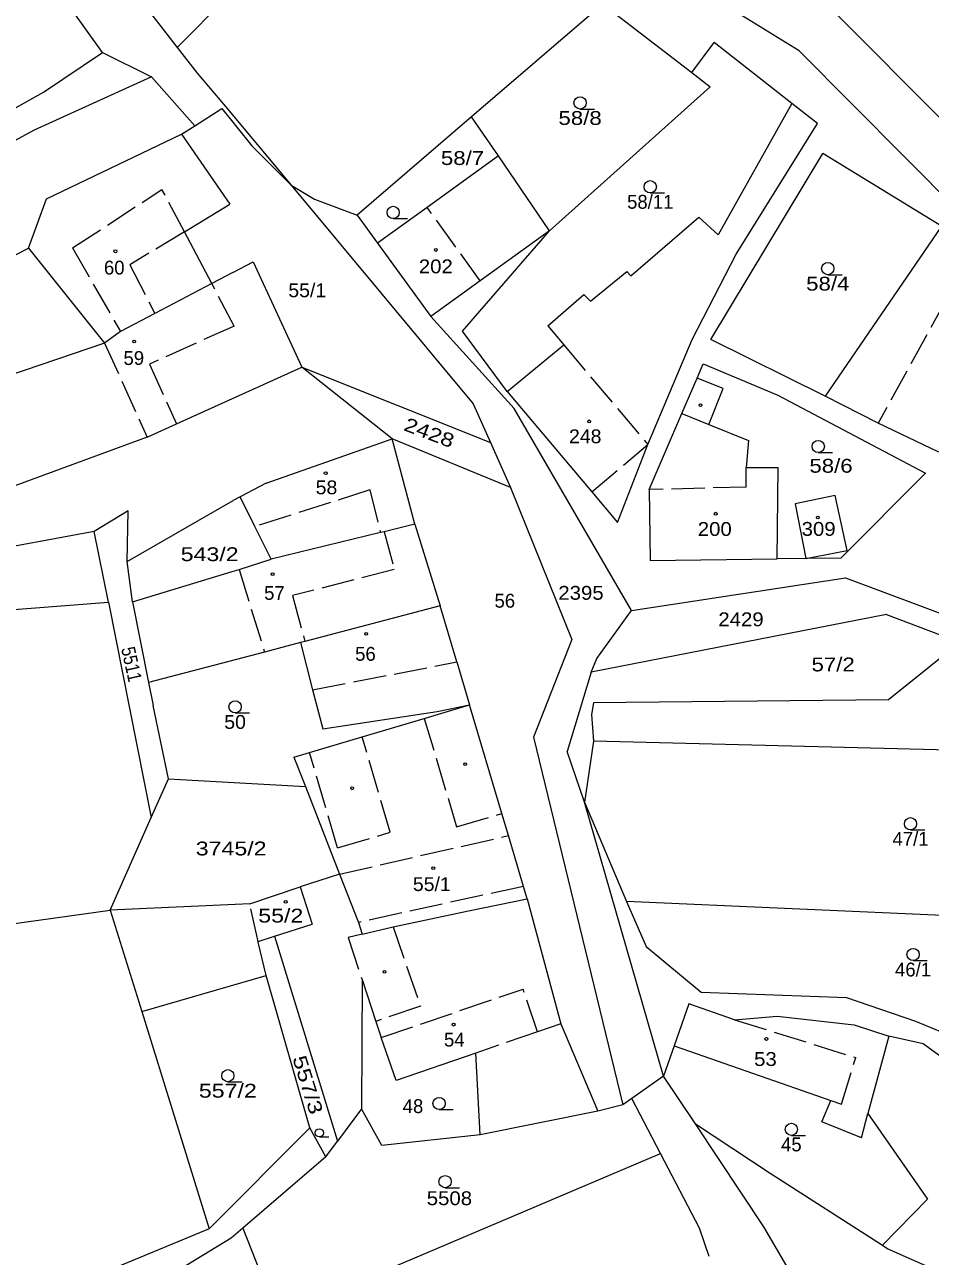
# Model space of a CAD drawing. Extents: x -590528 to -586543, y -1119609 to -1116685.
# Drawn here: x -589346.9 to -589235.8, y -1118589.8 to -1118438.6 of the extents above; entities that cross this region are included whole.
import ezdxf
from ezdxf.enums import TextEntityAlignment as Align

# ---------------------------------------------------------------- set-up
doc = ezdxf.new("R2010")
doc.units = 0
doc.header["$LTSCALE"] = 0.68
doc.linetypes.add('LONG_DASHED', pattern=[7.5, 6, -1.5])
for name, color, linetype, lineweight in [('1', 7, 'Continuous', 13), ('2', 7, 'LONG_DASHED', 13), ('3', 7, 'Continuous', 13), ('6', 7, 'Continuous', 13)]:
    doc.layers.add(name, color=color, linetype=linetype, lineweight=lineweight)

msp = doc.modelspace()

# ---------------------------------------------------------------- linework, layer by layer
at = {"layer": '1'}
for p, q in [((-589328.21, -1118441.4), (-589299.45, -1118412.34)), ((-589251.89, -1118441.81), (-589270.14, -1118430.49)), ((-589275.98, -1118436.06), (-589292.08, -1118449.9)), ((-589265.05, -1118444.46), (-589262.3, -1118440.79)), ((-589252.79, -1118448.25), (-589262.3, -1118440.79)), ((-589337.38, -1118442.01), (-589331.37, -1118445.01)), ((-589223.13, -1118470.78), (-589251.89, -1118441.81)), ((-589326.06, -1118451), (-589331.37, -1118445.01)), ((-589282.5, -1118463.9), (-589262.78, -1118446.21)), ((-589252.79, -1118448.25), (-589261.82, -1118464.4)), ((-589249.64, -1118450.73), (-589252.79, -1118448.25)), ((-589326.06, -1118451), (-589322.72, -1118448.89)), ((-589322.72, -1118448.89), (-589319.07, -1118453.48)), ((-589322.29, -1118448.62), (-589314.24, -1118458.28)), ((-589292.08, -1118449.9), (-589306.11, -1118461.96)), ((-589327.69, -1118452.03), (-589326.06, -1118451)), ((-589259.62, -1118466.78), (-589249.64, -1118450.73)), ((-589344.24, -1118459.99), (-589327.69, -1118452.03)), ((-589327.69, -1118452.03), (-589321.76, -1118460.61)), ((-589319.07, -1118453.48), (-589314.24, -1118458.28)), ((-589262.71, -1118477.26), (-589248.96, -1118454.42)), ((-589234.42, -1118463.35), (-589248.96, -1118454.42)), ((-589288.79, -1118454.71), (-589297.53, -1118461.03)), ((-589314.24, -1118458.28), (-589311.35, -1118460)), ((-589314.24, -1118458.28), (-589291.88, -1118485.15)), ((-589346.46, -1118466.02), (-589344.24, -1118459.99)), ((-589327.33, -1118464.02), (-589321.76, -1118460.61)), ((-589311.35, -1118460), (-589306.11, -1118461.96)), ((-589306.11, -1118461.96), (-589303.61, -1118465.42)), ((-589297.53, -1118461.03), (-589303.61, -1118465.42)), ((-589272.53, -1118469.41), (-589264.2, -1118462.23)), ((-589261.82, -1118464.4), (-589264.2, -1118462.23)), ((-589234.42, -1118463.35), (-589248.67, -1118484.2)), ((-589323.97, -1118470.39), (-589327.33, -1118464.02)), ((-589356.8, -1118471.32), (-589346.46, -1118466.02)), ((-589346.46, -1118466.02), (-589337.12, -1118477.71)), ((-589303.61, -1118465.42), (-589297.09, -1118474.44)), ((-589321.38, -1118469.03), (-589318.87, -1118467.73)), ((-589318.87, -1118467.73), (-589312.9, -1118480.66)), ((-589321.38, -1118469.03), (-589323.97, -1118470.39)), ((-589277.5, -1118472.53), (-589273.01, -1118468.89)), ((-589272.53, -1118469.41), (-589273.01, -1118468.89)), ((-589282.73, -1118475.56), (-589278.29, -1118471.74)), ((-589278.29, -1118471.74), (-589277.5, -1118472.53)), ((-589297.09, -1118474.44), (-589286.87, -1118485.7)), ((-589282.73, -1118475.56), (-589280.75, -1118477.91)), ((-589248.67, -1118484.2), (-589262.71, -1118477.26)), ((-589287.73, -1118483.63), (-589280.75, -1118477.91)), ((-589264.4, -1118482), (-589263.64, -1118480.25)), ((-589263.64, -1118480.25), (-589254.47, -1118484.08)), ((-589328.3, -1118487.6), (-589312.9, -1118480.66)), ((-589312.9, -1118480.66), (-589289.75, -1118489.91)), ((-589301.82, -1118489.46), (-589312.9, -1118480.66)), ((-589261.2, -1118483.28), (-589264.4, -1118482)), ((-589262.96, -1118487.68), (-589261.2, -1118483.28)), ((-589287.73, -1118483.63), (-589277.34, -1118495.95)), ((-589254.47, -1118484.08), (-589236.35, -1118493.64)), ((-589272.44, -1118510.52), (-589286.87, -1118485.7)), ((-589331.9, -1118489.22), (-589328.3, -1118487.6)), ((-589262.96, -1118487.68), (-589258.1, -1118489.64)), ((-589331.9, -1118489.22), (-589348.93, -1118495.49)), ((-589317.29, -1118494.88), (-589301.82, -1118489.46)), ((-589287.29, -1118495.4), (-589301.82, -1118489.46)), ((-589299.03, -1118499.91), (-589301.82, -1118489.46)), ((-589258.1, -1118489.64), (-589258.36, -1118492.97)), ((-589258.36, -1118492.97), (-589254.46, -1118492.97)), ((-589254.56, -1118504.19), (-589254.46, -1118492.97)), ((-589246.76, -1118504.1), (-589236.35, -1118493.64)), ((-589287.29, -1118495.4), (-589279.79, -1118514.08)), ((-589318.67, -1118500.22), (-589320.5, -1118496.58)), ((-589270.3, -1118495.68), (-589270.17, -1118504.37)), ((-589334.35, -1118504.49), (-589321.35, -1118497.03)), ((-589299.03, -1118499.91), (-589295.93, -1118509.94)), ((-589316.66, -1118504.23), (-589318.67, -1118500.22)), ((-589303.25, -1118500.95), (-589316.66, -1118504.23)), ((-589320.61, -1118505.47), (-589316.66, -1118504.23)), ((-589270.17, -1118504.37), (-589254.56, -1118504.19)), ((-589333.72, -1118509.47), (-589334.35, -1118504.49)), ((-589272.44, -1118510.52), (-589246.17, -1118506.49)), ((-589246.17, -1118506.49), (-589194.73, -1118525.89)), ((-589336.66, -1118509.48), (-589331.39, -1118535.93)), ((-589295.93, -1118509.94), (-589312.54, -1118514.31)), ((-589293.89, -1118516.82), (-589295.93, -1118509.94)), ((-589313.09, -1118514.46), (-589317.5, -1118515.62)), ((-589312.54, -1118514.31), (-589313.09, -1118514.46)), ((-589317.5, -1118515.62), (-589331.72, -1118519.37)), ((-589293.89, -1118516.82), (-589292.32, -1118522.11)), ((-589329.29, -1118531.2), (-589331.15, -1118522.18)), ((-589296.31, -1118522.91), (-589292.32, -1118522.11)), ((-589288.37, -1118535.44), (-589292.32, -1118522.11)), ((-589310.35, -1118525.04), (-589296.31, -1118522.91)), ((-589311.97, -1118527.94), (-589305.51, -1118526.04)), ((-589313.89, -1118528.51), (-589311.97, -1118527.94)), ((-589331.39, -1118535.93), (-589329.29, -1118531.2)), ((-589329.29, -1118531.2), (-589312.47, -1118532.14)), ((-589278.21, -1118534.03), (-589273.08, -1118546.25)), ((-589268.54, -1118567.69), (-589278.21, -1118534.03)), ((-589336.43, -1118547.3), (-589331.39, -1118535.93)), ((-589319.3, -1118546.53), (-589313.13, -1118544.43)), ((-589285.26, -1118545.92), (-589285.71, -1118544.39)), ((-589292.47, -1118547.41), (-589285.26, -1118545.92)), ((-589285.26, -1118545.92), (-589281.14, -1118561.27)), ((-589216.13, -1118548.79), (-589273.08, -1118546.25)), ((-589383.31, -1118553.86), (-589336.43, -1118547.3)), ((-589316.26, -1118550.49), (-589311.66, -1118549.04)), ((-589317.31, -1118555.33), (-589318.26, -1118551.24)), ((-589316.26, -1118550.49), (-589308.55, -1118575.69)), ((-589332.55, -1118559.77), (-589317.31, -1118555.33)), ((-589305.52, -1118555.84), (-589305.58, -1118571.71)), ((-589263.88, -1118557.38), (-589246.06, -1118558.05)), ((-589259.8, -1118560.76), (-589265.43, -1118558.8)), ((-589246.06, -1118558.05), (-589237.59, -1118560.95)), ((-589281.14, -1118561.27), (-589276.6, -1118571.99)), ((-589301.34, -1118568.23), (-589303.17, -1118562.94)), ((-589240.88, -1118562.79), (-589243.44, -1118572.29)), ((-589291.54, -1118564.85), (-589301.34, -1118568.23)), ((-589291.01, -1118574.89), (-589291.54, -1118564.85)), ((-589267.22, -1118563.95), (-589247.99, -1118570.67)), ((-589268.54, -1118567.69), (-589272.41, -1118570.43)), ((-589264.6, -1118573.55), (-589268.54, -1118567.69)), ((-589249.1, -1118573.3), (-589247.99, -1118570.67)), ((-589305.58, -1118571.71), (-589308.55, -1118575.69)), ((-589303.09, -1118576.19), (-589305.58, -1118571.71)), ((-589276.6, -1118571.99), (-589291.01, -1118574.89)), ((-589244.21, -1118575.27), (-589243.44, -1118572.29)), ((-589243.44, -1118572.29), (-589236.12, -1118582.79)), ((-589309.95, -1118577.58), (-589311.95, -1118574.03)), ((-589264.6, -1118573.55), (-589255.44, -1118579.6)), ((-589256.21, -1118586.19), (-589264.6, -1118573.55)), ((-589244.21, -1118575.27), (-589249.1, -1118573.3)), ((-589291.01, -1118574.89), (-589303.09, -1118576.19)), ((-589309.95, -1118577.58), (-589308.55, -1118575.69)), ((-589236.12, -1118582.79), (-589241.66, -1118588.45)), ((-589324.31, -1118586.45), (-589356.56, -1118599.76)), ((-589247.54, -1118601.02), (-589256.21, -1118586.19)), ((-589240.99, -1118588.88), (-589215.68, -1118600.1))]:
    msp.add_line(p, q, dxfattribs=at)
for points in [[(-589374.32, -1118404.86), (-589380.45, -1118462.92), (-589374.76, -1118462.64), (-589367.9, -1118459.92), (-589356.04, -1118453.27), (-589344.63, -1118446.86), (-589337.38, -1118442.01), (-589341.33, -1118436.52), (-589346.1, -1118428.33), (-589348.05, -1118422.4)], [(-589340.63, -1118423.61), (-589338.2, -1118428.36), (-589334.98, -1118432.65), (-589328.21, -1118441.4), (-589325.78, -1118444.54), (-589322.29, -1118448.62)], [(-589275.98, -1118436.06), (-589265.05, -1118444.46), (-589262.78, -1118446.21)], [(-589247.08, -1118437.51), (-589221.83, -1118462.82), (-589205.62, -1118461.09)], [(-589331.37, -1118445.01), (-589345.78, -1118451.54), (-589354.64, -1118456.32), (-589365.2, -1118462.01), (-589373.54, -1118466.17), (-589383.43, -1118465.99)], [(-589282.5, -1118463.9), (-589288.79, -1118454.71), (-589292.08, -1118449.9)], [(-589282.5, -1118463.9), (-589291.01, -1118470.05), (-589297.09, -1118474.44)], [(-589287.73, -1118483.63), (-589293.19, -1118476.22), (-589282.5, -1118463.9)], [(-589270.45, -1118490.15), (-589265.01, -1118477.24), (-589259.62, -1118466.78)], [(-589323.97, -1118470.39), (-589330.95, -1118474.06), (-589335.16, -1118476.28)], [(-589335.16, -1118476.28), (-589337.12, -1118477.71), (-589352.94, -1118483.06)], [(-589270.3, -1118495.68), (-589266.28, -1118486.35), (-589264.4, -1118482)], [(-589234.74, -1118491.09), (-589242.18, -1118487.51), (-589248.67, -1118484.2)], [(-589291.88, -1118485.15), (-589289.75, -1118489.91), (-589287.29, -1118495.4)], [(-589277.34, -1118495.95), (-589274.18, -1118499.7), (-589270.45, -1118490.15)], [(-589317.29, -1118494.88), (-589320.5, -1118496.58), (-589321.35, -1118497.03)], [(-589334.35, -1118504.49), (-589334.24, -1118498.3), (-589338.42, -1118500.8)], [(-589299.03, -1118499.91), (-589302.8, -1118500.84), (-589303.25, -1118500.95)], [(-589246.76, -1118504.1), (-589251.06, -1118504.15), (-589254.56, -1118504.19)], [(-589333.72, -1118509.47), (-589321.48, -1118505.74), (-589320.61, -1118505.47)], [(-589333.72, -1118509.47), (-589331.72, -1118519.37), (-589331.15, -1118522.18)], [(-589277.4, -1118518.07), (-589276.72, -1118516.4), (-589272.44, -1118510.52)], [(-589241.14, -1118511.02), (-589277.4, -1118518.07), (-589280.33, -1118527.81)], [(-589241.14, -1118511.02), (-589217.51, -1118519.97), (-589233.4, -1118515.49), (-589240.89, -1118521.5), (-589277.12, -1118521.87)], [(-589313.09, -1118514.46), (-589311.59, -1118520.27), (-589310.35, -1118525.04)], [(-589279.79, -1118514.08), (-589284.48, -1118526.07), (-589273.52, -1118571.22)], [(-589305.51, -1118526.04), (-589297.88, -1118523.77), (-589292.32, -1118522.11)], [(-589277.12, -1118521.87), (-589277.37, -1118523.27), (-589277.11, -1118526.56)], [(-589277.11, -1118526.56), (-589278.21, -1118534.03), (-589280.33, -1118527.81)], [(-589196.14, -1118528.59), (-589200.26, -1118526.5), (-589213.96, -1118528.14), (-589277.11, -1118526.56)], [(-589313.89, -1118528.51), (-589312.47, -1118532.14), (-589308.28, -1118542.88), (-589305.97, -1118548.81)], [(-589285.71, -1118544.39), (-589287.56, -1118538.16), (-589288.37, -1118535.44)], [(-589308.28, -1118542.88), (-589313.13, -1118544.43), (-589311.66, -1118549.04)], [(-589319.3, -1118546.53), (-589336.43, -1118547.3), (-589332.55, -1118559.77), (-589324.31, -1118586.45)], [(-589273.08, -1118546.25), (-589270.65, -1118551.77), (-589263.88, -1118557.38)], [(-589305.97, -1118548.81), (-589305.5, -1118550.25), (-589301.71, -1118549.35), (-589292.47, -1118547.41)], [(-589318.26, -1118551.24), (-589318.28, -1118551.14), (-589316.26, -1118550.49)], [(-589324.31, -1118586.45), (-589311.95, -1118574.03), (-589317.31, -1118555.33)], [(-589305.52, -1118555.84), (-589303.82, -1118560.96), (-589303.17, -1118562.94)], [(-589265.43, -1118558.8), (-589267.22, -1118563.95), (-589268.54, -1118567.69)], [(-589259.8, -1118560.76), (-589254.56, -1118560.32), (-589245.11, -1118561.39), (-589240.88, -1118562.79)], [(-589237.59, -1118560.95), (-589230.48, -1118563.88), (-589228.21, -1118564.82)], [(-589220.61, -1118575.41), (-589222.63, -1118573.97), (-589225.96, -1118571.65), (-589227.74, -1118570.24), (-589236.64, -1118563.74), (-589240.88, -1118562.79)], [(-589320.16, -1118586.37), (-589315.9, -1118597.15), (-589268.88, -1118577.2), (-589272.41, -1118570.43)], [(-589272.41, -1118570.43), (-589273.52, -1118571.22), (-589276.6, -1118571.99)], [(-589309.95, -1118577.58), (-589320.16, -1118586.37), (-589321.57, -1118587.58)], [(-589262.93, -1118589.84), (-589264.1, -1118586.37), (-589268.88, -1118577.2)], [(-589255.44, -1118579.6), (-589241.66, -1118588.45), (-589240.99, -1118588.88)], [(-589321.57, -1118587.58), (-589326.81, -1118590.78), (-589339.12, -1118597.03), (-589355.39, -1118602.34), (-589372.18, -1118605.52)]]:
    msp.add_lwpolyline(points, dxfattribs=at)
for points in [[(-589245.97, -1118503.14), (-589247.46, -1118496.38), (-589252.37, -1118497.43), (-589251.06, -1118504.15)], [(-589336.66, -1118509.48), (-589338.42, -1118500.8), (-589348.14, -1118502.62), (-589364.48, -1118504.62), (-589366.99, -1118507.07), (-589371.5, -1118512.2)]]:
    msp.add_lwpolyline(points, close=True, dxfattribs=at)
at = {"layer": '2'}
for p, q in [((-589341.05, -1118466.01), (-589330.08, -1118458.81)), ((-589327.33, -1118464.02), (-589330.08, -1118458.81)), ((-589291.01, -1118470.05), (-589297.53, -1118461.03)), ((-589341.05, -1118466.01), (-589335.16, -1118476.28)), ((-589321.23, -1118475.59), (-589323.97, -1118470.39)), ((-589233.74, -1118472.21), (-589242.18, -1118487.51)), ((-589321.23, -1118475.59), (-589331.6, -1118480.26)), ((-589337.12, -1118477.71), (-589331.9, -1118489.22)), ((-589280.75, -1118477.91), (-589270.45, -1118490.15)), ((-589331.6, -1118480.26), (-589328.3, -1118487.6)), ((-589266.28, -1118486.35), (-589262.96, -1118487.68)), ((-589277.34, -1118495.95), (-589270.45, -1118490.15)), ((-589258.36, -1118495.37), (-589258.36, -1118492.97)), ((-589258.36, -1118495.37), (-589270.3, -1118495.68)), ((-589304.55, -1118495.71), (-589318.67, -1118500.22)), ((-589304.55, -1118495.71), (-589303.25, -1118500.95)), ((-589302.8, -1118500.84), (-589301.58, -1118505.49)), ((-589320.61, -1118505.47), (-589317.5, -1118515.62)), ((-589311.59, -1118520.27), (-589293.89, -1118516.82)), ((-589302.07, -1118537.75), (-589305.51, -1118526.04)), ((-589308.53, -1118539.65), (-589311.97, -1118527.94)), ((-589308.53, -1118539.65), (-589302.07, -1118537.75)), ((-589308.28, -1118542.88), (-589287.56, -1118538.16)), ((-589285.71, -1118544.39), (-589305.97, -1118548.81)), ((-589318.28, -1118551.14), (-589319.3, -1118546.53)), ((-589301.71, -1118549.35), (-589298.36, -1118559.08)), ((-589303.17, -1118562.94), (-589285.75, -1118557)), ((-589298.36, -1118559.08), (-589303.82, -1118560.96)), ((-589259.8, -1118560.76), (-589244.93, -1118565.4)), ((-589283.97, -1118562.24), (-589291.54, -1118564.85)), ((-589246.69, -1118571.12), (-589244.93, -1118565.4)), ((-589247.99, -1118570.67), (-589246.69, -1118571.12))]:
    msp.add_line(p, q, dxfattribs=at)
for points in [[(-589327.33, -1118464.02), (-589334.04, -1118468.09), (-589330.95, -1118474.06)], [(-589301.58, -1118505.49), (-589314.05, -1118508.69), (-589312.54, -1118514.31)], [(-589297.88, -1118523.77), (-589293.92, -1118537.09), (-589288.37, -1118535.44)], [(-589305.5, -1118550.25), (-589307.23, -1118550.68), (-589305.52, -1118555.84)], [(-589281.14, -1118561.27), (-589283.97, -1118562.24), (-589285.75, -1118557)]]:
    msp.add_lwpolyline(points, dxfattribs=at)
at = {"layer": '6'}
for p, q in [((-589278.76, -1118448.95), (-589277.01, -1118448.95)), ((-589270.15, -1118459.24), (-589268.4, -1118459.24)), ((-589301.7, -1118462.39), (-589299.95, -1118462.39)), ((-589248.36, -1118469.29), (-589246.61, -1118469.29)), ((-589249.53, -1118491.13), (-589247.78, -1118491.13)), ((-589321.11, -1118523.1), (-589319.36, -1118523.1)), ((-589238.2, -1118537.45), (-589236.45, -1118537.45)), ((-589237.89, -1118553.5), (-589236.14, -1118553.5)), ((-589322, -1118568.38), (-589320.25, -1118568.38)), ((-589296.07, -1118571.79), (-589294.32, -1118571.79)), ((-589310.76, -1118575.152), (-589309.588, -1118575.152)), ((-589252.83, -1118574.97), (-589251.08, -1118574.97)), ((-589295.33, -1118581.39), (-589293.58, -1118581.39))]:
    msp.add_line(p, q, dxfattribs=at)
for centre, radius in [((-589278.76, -1118448.2), 0.75), ((-589270.15, -1118458.49), 0.75), ((-589301.7, -1118461.64), 0.75), ((-589335.8002, -1118466.4204), 0.175), ((-589296.4702, -1118466.2504), 0.175), ((-589248.36, -1118468.54), 0.75), ((-589333.4902, -1118477.4904), 0.175), ((-589263.9802, -1118485.3104), 0.175), ((-589277.6502, -1118487.3004), 0.175), ((-589249.53, -1118490.38), 0.75), ((-589309.9902, -1118493.6504), 0.175), ((-589262.1102, -1118498.6304), 0.175), ((-589249.5802, -1118499.0904), 0.175), ((-589316.5002, -1118506.0504), 0.175), ((-589305.0202, -1118513.3804), 0.175), ((-589321.11, -1118522.35), 0.75), ((-589292.8602, -1118529.3804), 0.175), ((-589306.7302, -1118532.3504), 0.175), ((-589238.2, -1118536.7), 0.75), ((-589296.7802, -1118542.1604), 0.175), ((-589314.8902, -1118546.2904), 0.175), ((-589237.89, -1118552.75), 0.75), ((-589302.7702, -1118554.8804), 0.175), ((-589294.2902, -1118561.3604), 0.175), ((-589255.9002, -1118563.1204), 0.175), ((-589322, -1118567.63), 0.75), ((-589296.07, -1118571.04), 0.75), ((-589252.83, -1118574.22), 0.75), ((-589310.76, -1118574.65), 0.5025), ((-589295.33, -1118580.64), 0.75)]:
    msp.add_circle(centre, radius, dxfattribs=at)

# ---------------------------------------------------------------- texts
at = {"layer": '3'}
for s, width, p in [('58/8', 1.2, (-589278.7605, -1118450.9)), ('58/7', 1.2, (-589293.19, -1118455.82)), ('202', 1.1, (-589296.47, -1118469.12)), ('58/4', 1.2, (-589248.36, -1118471.24)), ('55/1', 1.05, (-589312.2505, -1118472.05)), ('248', 1.05, (-589278.13, -1118489.98)), ('58/6', 1.2, (-589247.96, -1118493.6)), ('58', 1.05, (-589309.8905, -1118496.25)), ('200', 1.1, (-589262.23, -1118501.36)), ('309', 1.1, (-589249.4805, -1118501.35)), ('543/2', 1.25, (-589324.2305, -1118504.46)), ('2395', 1.1, (-589278.6505, -1118509.2)), ('2429', 1.1, (-589259.0105, -1118512.45)), ('57/2', 1.2, (-589247.7, -1118517.99)), ('50', 1.05, (-589321.111, -1118525.05)), ('3745/2', 1.25, (-589321.5905, -1118540.59)), ('55/1', 1.05, (-589296.9605, -1118544.96)), ('55/2', 1.25, (-589315.5, -1118548.83)), ('53', 1.1, (-589256.0105, -1118566.44)), ('557/2', 1.25, (-589322, -1118570.33))]:
    msp.add_text(s, height=1.7, dxfattribs=dict(at, width=width)).set_placement(p, align=Align.CENTER)
for s, p in [('58/11', (-589270.1505, -1118461.19)), ('60', (-589335.9405, -1118469.27)), ('59', (-589333.5405, -1118480.37)), ('57', (-589316.2805, -1118509.21)), ('56', (-589288.0005, -1118510.17)), ('56', (-589305.1105, -1118516.69)), ('47/1', (-589238.2005, -1118539.4)), ('46/1', (-589237.8905, -1118555.45)), ('54', (-589294.2005, -1118564.05)), ('48', (-589299.27, -1118572.22)), ('45', (-589252.8305, -1118576.92))]:
    msp.add_text(s, height=1.7, dxfattribs=at).set_placement(p, align=Align.CENTER)
for s, rotation, width, p in [('2428', 339.306, 1.25, (-589297.5694, -1118489.4737)), ('557/3', 287.224, 1.3, (-589312.9917, -1118569.0013))]:
    msp.add_text(s, height=1.7, rotation=rotation, dxfattribs=dict(at, width=width)).set_placement(p, align=Align.CENTER)
at = {"layer": '3', "width": 0.85}
msp.add_text('5511', height=1.7, rotation=282.583, dxfattribs=at).set_placement((-589335.108, -1118515.192))
at = {"layer": '3', "width": 1.1}
msp.add_text('5508', height=1.7, dxfattribs=at).set_placement((-589297.583, -1118583.53))

doc.saveas('drawing.dxf')
